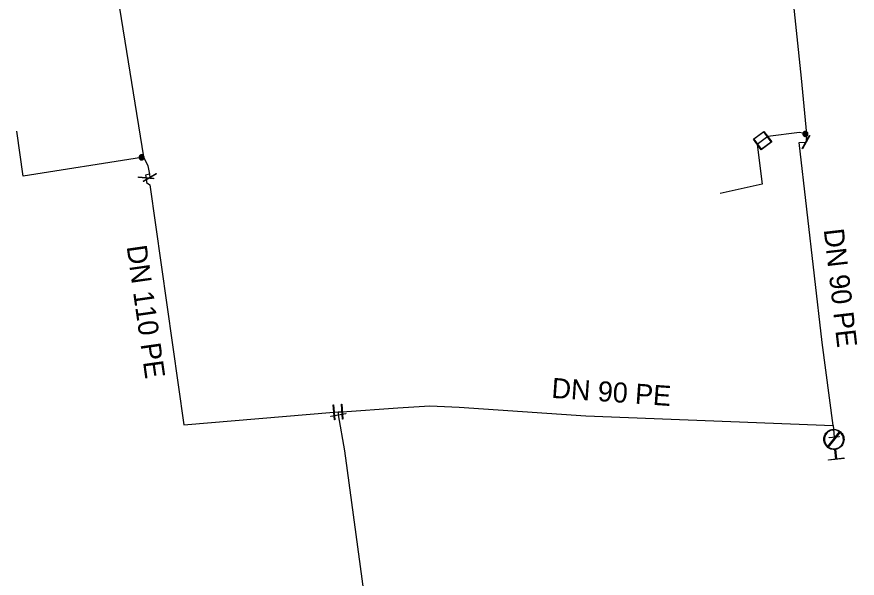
# Model space of a CAD drawing. Extents: x -832382 to -831581, y -1074670 to -1074251.
# Drawn here: x -831959.2 to -831875.6, y -1074502.9 to -1074447.1 of the extents above; entities that cross this region are included whole.
import ezdxf

# ---------------------------------------------------------------- set-up
doc = ezdxf.new("R2010")
doc.units = 0
for name, color, linetype in [('Hyd-odbočka', 7, 'Continuous'), ('Hyd-šoupě', 7, 'Continuous'), ('Hydrant', 7, 'Continuous'), ('Přípojka vodovodu', 7, 'Continuous'), ('Přípojkový uzávěr', 7, 'Continuous'), ('Roz-řad', 7, 'Continuous'), ('Roz-řad-popis základní', 7, 'Continuous'), ('Řad-šoupě', 7, 'Continuous'), ('Šachta vodovodní', 7, 'Continuous')]:
    doc.layers.add(name, color=color, linetype=linetype)

msp = doc.modelspace()

# ---------------------------------------------------------------- linework, layer by layer
at = {"layer": 'Hyd-odbočka'}
for p, q in [((-831877.96, -1074487.73), (-831877.84, -1074488.88)), ((-831877.84, -1074488.88), (-831877.88, -1074489.11))]:
    msp.add_line(p, q, dxfattribs=at)
at = {"layer": 'Hyd-šoupě'}
msp.add_lwpolyline([(-831878.339, -1074488.916), (-831877.344, -1074488.813), (-831877.341, -1074488.844), (-831878.336, -1074488.947), (-831878.339, -1074488.916)], dxfattribs=at)
at = {"layer": 'Hydrant'}
for points in [[(-831878.487, -1074489.827), (-831877.321, -1074488.353)], [(-831877.273, -1074488.393), (-831878.439, -1074489.865)], [(-831877.734, -1074490.1), (-831877.625, -1074491.031), (-831876.88, -1074490.944), (-831876.873, -1074491.006), (-831878.425, -1074491.187), (-831878.432, -1074491.125), (-831877.687, -1074491.038), (-831877.796, -1074490.107)]]:
    msp.add_lwpolyline(points, dxfattribs=at)
for points in [[(-831877.796, -1074490.107), (-831878.031, -1074490.126), (-831878.268, -1074490.032), (-831878.52, -1074489.932), (-831878.682, -1074489.708), (-831878.843, -1074489.485), (-831878.873, -1074489.225), (-831878.903, -1074488.967), (-831878.8, -1074488.715), (-831878.696, -1074488.464), (-831878.475, -1074488.305), (-831878.253, -1074488.147), (-831877.995, -1074488.117), (-831877.737, -1074488.087), (-831877.485, -1074488.19), (-831877.234, -1074488.294), (-831877.075, -1074488.515), (-831876.917, -1074488.737), (-831876.887, -1074488.995), (-831876.856, -1074489.255), (-831876.963, -1074489.509), (-831877.069, -1074489.763), (-831877.291, -1074489.918), (-831877.498, -1074490.064), (-831877.734, -1074490.1)], [(-831877.321, -1074488.353), (-831877.407, -1074488.29), (-831877.51, -1074488.249), (-831877.746, -1074488.151), (-831877.988, -1074488.179), (-831878.231, -1074488.207), (-831878.439, -1074488.356), (-831878.646, -1074488.505), (-831878.743, -1074488.74), (-831878.839, -1074488.976), (-831878.811, -1074489.218), (-831878.783, -1074489.463), (-831878.631, -1074489.671), (-831878.565, -1074489.76), (-831878.487, -1074489.827)], [(-831878.439, -1074489.865), (-831878.349, -1074489.931), (-831878.244, -1074489.974), (-831878.007, -1074490.069), (-831877.772, -1074490.041), (-831877.537, -1074490.014), (-831877.328, -1074489.868), (-831877.119, -1074489.722), (-831877.02, -1074489.484), (-831876.92, -1074489.246), (-831876.949, -1074489.002), (-831876.977, -1074488.759), (-831877.127, -1074488.553), (-831877.19, -1074488.462), (-831877.273, -1074488.393)]]:
    msp.add_open_spline(points, degree=3, dxfattribs=at)
at = {"layer": 'Přípojka vodovodu'}
for points in [[(-831946.578, -1074461.011), (-831946.757, -1074461.052), (-831958.538, -1074462.927), (-831959.174, -1074458.455)], [(-831880.618, -1074458.746), (-831880.72, -1074458.72), (-831881.288, -1074458.576), (-831884.45, -1074458.99), (-831884.983, -1074459.375)], [(-831884.983, -1074459.375), (-831885.53, -1074459.77), (-831885.03, -1074463.72), (-831889.21, -1074464.66)]]:
    msp.add_lwpolyline(points, dxfattribs=at)
at = {"layer": 'Přípojkový uzávěr'}
for points in [[(-831880.72, -1074458.47), (-831880.657, -1074458.47), (-831880.597, -1074458.502), (-831880.538, -1074458.534), (-831880.504, -1074458.595), (-831880.47, -1074458.655), (-831880.47, -1074458.72), (-831880.47, -1074458.785), (-831880.503, -1074458.845), (-831880.536, -1074458.904), (-831880.595, -1074458.937), (-831880.655, -1074458.97), (-831880.72, -1074458.97), (-831880.785, -1074458.97), (-831880.845, -1074458.937), (-831880.904, -1074458.904), (-831880.937, -1074458.845), (-831880.97, -1074458.785), (-831880.97, -1074458.72), (-831880.97, -1074458.655), (-831880.936, -1074458.595), (-831880.903, -1074458.534), (-831880.843, -1074458.502), (-831880.783, -1074458.47), (-831880.72, -1074458.47)], [(-831880.72, -1074458.493), (-831880.777, -1074458.493), (-831880.832, -1074458.523), (-831880.886, -1074458.552), (-831880.916, -1074458.606), (-831880.947, -1074458.661), (-831880.947, -1074458.72), (-831880.947, -1074458.779), (-831880.917, -1074458.833), (-831880.887, -1074458.887), (-831880.833, -1074458.917), (-831880.779, -1074458.947), (-831880.72, -1074458.947), (-831880.661, -1074458.947), (-831880.607, -1074458.917), (-831880.553, -1074458.887), (-831880.523, -1074458.833), (-831880.493, -1074458.779), (-831880.493, -1074458.72), (-831880.493, -1074458.661), (-831880.524, -1074458.606), (-831880.555, -1074458.552), (-831880.609, -1074458.523), (-831880.663, -1074458.493), (-831880.72, -1074458.493)], [(-831880.72, -1074458.511), (-831880.667, -1074458.511), (-831880.617, -1074458.538), (-831880.567, -1074458.564), (-831880.539, -1074458.615), (-831880.511, -1074458.665), (-831880.511, -1074458.72), (-831880.511, -1074458.775), (-831880.538, -1074458.824), (-831880.565, -1074458.874), (-831880.616, -1074458.902), (-831880.666, -1074458.929), (-831880.72, -1074458.929), (-831880.774, -1074458.929), (-831880.824, -1074458.902), (-831880.875, -1074458.874), (-831880.902, -1074458.824), (-831880.929, -1074458.775), (-831880.929, -1074458.72), (-831880.929, -1074458.665), (-831880.901, -1074458.615), (-831880.873, -1074458.564), (-831880.823, -1074458.538), (-831880.773, -1074458.511), (-831880.72, -1074458.511)], [(-831880.72, -1074458.533), (-831880.799, -1074458.533), (-831880.853, -1074458.587), (-831880.908, -1074458.642), (-831880.908, -1074458.72), (-831880.908, -1074458.798), (-831880.853, -1074458.853), (-831880.798, -1074458.908), (-831880.72, -1074458.908), (-831880.642, -1074458.908), (-831880.587, -1074458.853), (-831880.533, -1074458.798), (-831880.533, -1074458.72), (-831880.533, -1074458.642), (-831880.587, -1074458.587), (-831880.642, -1074458.533), (-831880.72, -1074458.533)], [(-831880.72, -1074458.555), (-831880.652, -1074458.555), (-831880.604, -1074458.603), (-831880.556, -1074458.651), (-831880.556, -1074458.72), (-831880.556, -1074458.788), (-831880.604, -1074458.836), (-831880.652, -1074458.884), (-831880.72, -1074458.884), (-831880.789, -1074458.884), (-831880.837, -1074458.836), (-831880.885, -1074458.788), (-831880.885, -1074458.72), (-831880.885, -1074458.651), (-831880.837, -1074458.603), (-831880.789, -1074458.555), (-831880.72, -1074458.555)], [(-831880.72, -1074458.575), (-831880.781, -1074458.575), (-831880.823, -1074458.617), (-831880.865, -1074458.66), (-831880.865, -1074458.72), (-831880.865, -1074458.779), (-831880.823, -1074458.822), (-831880.781, -1074458.864), (-831880.72, -1074458.864), (-831880.661, -1074458.864), (-831880.618, -1074458.822), (-831880.576, -1074458.779), (-831880.576, -1074458.72), (-831880.576, -1074458.66), (-831880.618, -1074458.617), (-831880.66, -1074458.575), (-831880.72, -1074458.575)], [(-831880.72, -1074458.595), (-831880.668, -1074458.595), (-831880.631, -1074458.632), (-831880.595, -1074458.668), (-831880.595, -1074458.72), (-831880.595, -1074458.772), (-831880.632, -1074458.809), (-831880.668, -1074458.845), (-831880.72, -1074458.845), (-831880.772, -1074458.845), (-831880.808, -1074458.809), (-831880.845, -1074458.772), (-831880.845, -1074458.72), (-831880.845, -1074458.668), (-831880.809, -1074458.632), (-831880.772, -1074458.595), (-831880.72, -1074458.595)], [(-831880.72, -1074458.618), (-831880.762, -1074458.618), (-831880.792, -1074458.648), (-831880.822, -1074458.678), (-831880.822, -1074458.72), (-831880.822, -1074458.762), (-831880.792, -1074458.792), (-831880.762, -1074458.821), (-831880.72, -1074458.821), (-831880.678, -1074458.821), (-831880.648, -1074458.792), (-831880.619, -1074458.762), (-831880.619, -1074458.72), (-831880.619, -1074458.678), (-831880.648, -1074458.648), (-831880.678, -1074458.618), (-831880.72, -1074458.618)], [(-831880.72, -1074458.636), (-831880.685, -1074458.636), (-831880.661, -1074458.66), (-831880.636, -1074458.685), (-831880.636, -1074458.72), (-831880.636, -1074458.755), (-831880.661, -1074458.779), (-831880.685, -1074458.804), (-831880.72, -1074458.804), (-831880.755, -1074458.804), (-831880.78, -1074458.779), (-831880.804, -1074458.755), (-831880.804, -1074458.72), (-831880.804, -1074458.685), (-831880.78, -1074458.66), (-831880.755, -1074458.636), (-831880.72, -1074458.636)], [(-831880.72, -1074458.658), (-831880.746, -1074458.658), (-831880.764, -1074458.676), (-831880.783, -1074458.694), (-831880.783, -1074458.72), (-831880.783, -1074458.746), (-831880.764, -1074458.764), (-831880.746, -1074458.783), (-831880.72, -1074458.783), (-831880.694, -1074458.783), (-831880.676, -1074458.764), (-831880.658, -1074458.746), (-831880.658, -1074458.72), (-831880.658, -1074458.694), (-831880.676, -1074458.676), (-831880.694, -1074458.658), (-831880.72, -1074458.658)], [(-831880.72, -1074458.681), (-831880.704, -1074458.681), (-831880.692, -1074458.692), (-831880.681, -1074458.703), (-831880.681, -1074458.72), (-831880.681, -1074458.736), (-831880.692, -1074458.748), (-831880.704, -1074458.759), (-831880.72, -1074458.759), (-831880.736, -1074458.759), (-831880.748, -1074458.748), (-831880.759, -1074458.736), (-831880.759, -1074458.72), (-831880.759, -1074458.703), (-831880.748, -1074458.692), (-831880.736, -1074458.681), (-831880.72, -1074458.681)], [(-831880.72, -1074458.697), (-831880.73, -1074458.697), (-831880.737, -1074458.703), (-831880.744, -1074458.71), (-831880.744, -1074458.72), (-831880.744, -1074458.73), (-831880.737, -1074458.737), (-831880.73, -1074458.743), (-831880.72, -1074458.743), (-831880.71, -1074458.743), (-831880.704, -1074458.737), (-831880.697, -1074458.73), (-831880.697, -1074458.72), (-831880.697, -1074458.71), (-831880.704, -1074458.703), (-831880.71, -1074458.697), (-831880.72, -1074458.697)], [(-831946.757, -1074460.802), (-831946.694, -1074460.802), (-831946.634, -1074460.834), (-831946.574, -1074460.866), (-831946.541, -1074460.927), (-831946.507, -1074460.987), (-831946.507, -1074461.052), (-831946.507, -1074461.117), (-831946.54, -1074461.177), (-831946.573, -1074461.236), (-831946.632, -1074461.269), (-831946.692, -1074461.302), (-831946.757, -1074461.302), (-831946.822, -1074461.302), (-831946.881, -1074461.269), (-831946.941, -1074461.236), (-831946.974, -1074461.177), (-831947.007, -1074461.117), (-831947.007, -1074461.052), (-831947.007, -1074460.987), (-831946.973, -1074460.927), (-831946.94, -1074460.866), (-831946.88, -1074460.834), (-831946.82, -1074460.802), (-831946.757, -1074460.802)], [(-831946.757, -1074460.825), (-831946.814, -1074460.825), (-831946.868, -1074460.855), (-831946.923, -1074460.884), (-831946.953, -1074460.938), (-831946.983, -1074460.993), (-831946.983, -1074461.052), (-831946.983, -1074461.111), (-831946.954, -1074461.165), (-831946.924, -1074461.219), (-831946.87, -1074461.249), (-831946.816, -1074461.279), (-831946.757, -1074461.279), (-831946.698, -1074461.279), (-831946.644, -1074461.249), (-831946.59, -1074461.219), (-831946.56, -1074461.165), (-831946.53, -1074461.111), (-831946.53, -1074461.052), (-831946.53, -1074460.993), (-831946.561, -1074460.938), (-831946.592, -1074460.884), (-831946.646, -1074460.855), (-831946.7, -1074460.825), (-831946.757, -1074460.825)], [(-831946.757, -1074460.842), (-831946.704, -1074460.842), (-831946.654, -1074460.869), (-831946.604, -1074460.896), (-831946.576, -1074460.947), (-831946.547, -1074460.997), (-831946.547, -1074461.052), (-831946.547, -1074461.107), (-831946.575, -1074461.156), (-831946.602, -1074461.206), (-831946.652, -1074461.234), (-831946.702, -1074461.261), (-831946.757, -1074461.261), (-831946.811, -1074461.261), (-831946.861, -1074461.234), (-831946.911, -1074461.206), (-831946.939, -1074461.156), (-831946.966, -1074461.107), (-831946.966, -1074461.052), (-831946.966, -1074460.997), (-831946.938, -1074460.947), (-831946.91, -1074460.896), (-831946.86, -1074460.869), (-831946.81, -1074460.842), (-831946.757, -1074460.842)], [(-831946.757, -1074460.864), (-831946.835, -1074460.864), (-831946.89, -1074460.919), (-831946.944, -1074460.974), (-831946.944, -1074461.052), (-831946.944, -1074461.13), (-831946.889, -1074461.185), (-831946.835, -1074461.239), (-831946.757, -1074461.239), (-831946.679, -1074461.239), (-831946.624, -1074461.185), (-831946.569, -1074461.13), (-831946.569, -1074461.052), (-831946.569, -1074460.974), (-831946.624, -1074460.919), (-831946.678, -1074460.864), (-831946.757, -1074460.864)], [(-831946.757, -1074460.887), (-831946.689, -1074460.887), (-831946.641, -1074460.935), (-831946.593, -1074460.983), (-831946.593, -1074461.051), (-831946.593, -1074461.12), (-831946.641, -1074461.168), (-831946.689, -1074461.216), (-831946.757, -1074461.216), (-831946.826, -1074461.216), (-831946.874, -1074461.168), (-831946.921, -1074461.12), (-831946.921, -1074461.051), (-831946.921, -1074460.983), (-831946.874, -1074460.935), (-831946.826, -1074460.887), (-831946.757, -1074460.887)], [(-831946.757, -1074460.907), (-831946.817, -1074460.907), (-831946.86, -1074460.949), (-831946.902, -1074460.992), (-831946.902, -1074461.051), (-831946.902, -1074461.111), (-831946.86, -1074461.154), (-831946.817, -1074461.196), (-831946.757, -1074461.196), (-831946.698, -1074461.196), (-831946.655, -1074461.154), (-831946.613, -1074461.111), (-831946.613, -1074461.051), (-831946.613, -1074460.992), (-831946.655, -1074460.949), (-831946.697, -1074460.907), (-831946.757, -1074460.907)], [(-831946.757, -1074460.927), (-831946.705, -1074460.927), (-831946.668, -1074460.964), (-831946.632, -1074461), (-831946.632, -1074461.052), (-831946.632, -1074461.104), (-831946.668, -1074461.14), (-831946.705, -1074461.177), (-831946.757, -1074461.177), (-831946.809, -1074461.177), (-831946.845, -1074461.14), (-831946.882, -1074461.104), (-831946.882, -1074461.052), (-831946.882, -1074461), (-831946.846, -1074460.964), (-831946.809, -1074460.927), (-831946.757, -1074460.927)], [(-831946.757, -1074460.95), (-831946.799, -1074460.95), (-831946.829, -1074460.98), (-831946.859, -1074461.009), (-831946.859, -1074461.052), (-831946.859, -1074461.094), (-831946.829, -1074461.124), (-831946.799, -1074461.153), (-831946.757, -1074461.153), (-831946.715, -1074461.153), (-831946.685, -1074461.124), (-831946.656, -1074461.094), (-831946.656, -1074461.052), (-831946.656, -1074461.009), (-831946.685, -1074460.98), (-831946.715, -1074460.95), (-831946.757, -1074460.95)], [(-831946.757, -1074460.967), (-831946.722, -1074460.967), (-831946.697, -1074460.992), (-831946.673, -1074461.017), (-831946.673, -1074461.052), (-831946.673, -1074461.087), (-831946.698, -1074461.111), (-831946.722, -1074461.136), (-831946.757, -1074461.136), (-831946.792, -1074461.136), (-831946.817, -1074461.111), (-831946.841, -1074461.087), (-831946.841, -1074461.052), (-831946.841, -1074461.017), (-831946.817, -1074460.992), (-831946.792, -1074460.967), (-831946.757, -1074460.967)], [(-831946.757, -1074460.989), (-831946.783, -1074460.989), (-831946.801, -1074461.008), (-831946.819, -1074461.026), (-831946.819, -1074461.052), (-831946.819, -1074461.078), (-831946.801, -1074461.096), (-831946.783, -1074461.114), (-831946.757, -1074461.114), (-831946.731, -1074461.114), (-831946.713, -1074461.096), (-831946.694, -1074461.078), (-831946.694, -1074461.052), (-831946.694, -1074461.026), (-831946.713, -1074461.008), (-831946.731, -1074460.989), (-831946.757, -1074460.989)], [(-831946.757, -1074461.013), (-831946.741, -1074461.013), (-831946.729, -1074461.024), (-831946.718, -1074461.035), (-831946.718, -1074461.052), (-831946.718, -1074461.068), (-831946.729, -1074461.08), (-831946.741, -1074461.091), (-831946.757, -1074461.091), (-831946.773, -1074461.091), (-831946.785, -1074461.08), (-831946.796, -1074461.068), (-831946.796, -1074461.052), (-831946.796, -1074461.035), (-831946.785, -1074461.024), (-831946.773, -1074461.013), (-831946.757, -1074461.013)], [(-831946.757, -1074461.029), (-831946.767, -1074461.029), (-831946.774, -1074461.035), (-831946.781, -1074461.042), (-831946.781, -1074461.052), (-831946.781, -1074461.062), (-831946.774, -1074461.069), (-831946.767, -1074461.075), (-831946.757, -1074461.075), (-831946.747, -1074461.075), (-831946.74, -1074461.069), (-831946.734, -1074461.062), (-831946.734, -1074461.052), (-831946.734, -1074461.042), (-831946.74, -1074461.035), (-831946.747, -1074461.029), (-831946.757, -1074461.029)]]:
    msp.add_open_spline(points, degree=3, dxfattribs=at)
at = {"layer": 'Roz-řad'}
for p, q in [((-831927.62, -1074486.41), (-831927.2, -1074486.36)), ((-831927.2, -1074486.36), (-831927.19, -1074486.68))]:
    msp.add_line(p, q, dxfattribs=at)
for points in [[(-831886.44, -1074408.64), (-831905.34, -1074408.59), (-831920.63, -1074409.77), (-831929.6, -1074411.16), (-831944.61, -1074414.5), (-831953.4, -1074417.02), (-831952.245, -1074422.863), (-831952.065, -1074424.626), (-831951.81, -1074427.06), (-831950.24, -1074438.21), (-831949.124, -1074445.161), (-831946.578, -1074461.011), (-831946.13, -1074461.88)], [(-831886.33, -1074408.96), (-831885.87, -1074413.25), (-831884.276, -1074422.86), (-831884.29, -1074423.69), (-831883.62, -1074429.58), (-831883.1, -1074435.36), (-831882.54, -1074441.32), (-831882.147, -1074443.657), (-831881.13, -1074453.16), (-831880.618, -1074458.746), (-831880.65, -1074459.53)], [(-831926.8, -1074486.36), (-831921.28, -1074485.98), (-831918.08, -1074485.78), (-831915.18, -1074485.91), (-831902.56, -1074486.78), (-831877.96, -1074487.73), (-831879.04, -1074479.47), (-831881.34, -1074459.58), (-831880.65, -1074459.53)], [(-831946.13, -1074461.88), (-831945.98, -1074462.73), (-831945.93, -1074463.06)], [(-831945.98, -1074462.73), (-831946.36, -1074462.81), (-831946.32, -1074463.09)], [(-831946.32, -1074463.09), (-831946.28, -1074463.54), (-831945.93, -1074463.8), (-831942.55, -1074487.65), (-831927.62, -1074486.41)], [(-831927.2, -1074486.36), (-831926.99, -1074486.36), (-831926.8, -1074486.36)], [(-831927.19, -1074486.68), (-831926.56, -1074490.26), (-831924.14, -1074508.11), (-831924.1, -1074508.45), (-831921.14, -1074530.29), (-831921.1, -1074530.55), (-831919, -1074544.28), (-831918.72, -1074546.15), (-831918.69, -1074546.67)]]:
    msp.add_lwpolyline(points, dxfattribs=at)
at = {"layer": 'Řad-šoupě'}
for points in [[(-831880.259, -1074458.89), (-831881.001, -1074460.193), (-831881.041, -1074460.17), (-831880.299, -1074458.867), (-831880.259, -1074458.89)], [(-831947.065, -1074462.998), (-831945.571, -1074463.135), (-831945.575, -1074463.182), (-831947.069, -1074463.045), (-831947.065, -1074462.998)], [(-831946.59, -1074463.418), (-831945.294, -1074462.662), (-831945.27, -1074462.702), (-831946.566, -1074463.458), (-831946.59, -1074463.418)], [(-831927.577, -1074487.159), (-831927.71, -1074485.665), (-831927.663, -1074485.661), (-831927.53, -1074487.155), (-831927.577, -1074487.159)], [(-831926.829, -1074485.61), (-831926.725, -1074487.107), (-831926.771, -1074487.11), (-831926.875, -1074485.613), (-831926.829, -1074485.61)], [(-831926.447, -1074486.573), (-831927.925, -1074486.833), (-831927.933, -1074486.787), (-831926.455, -1074486.527), (-831926.447, -1074486.573)]]:
    msp.add_lwpolyline(points, dxfattribs=at)
at = {"layer": 'Šachta vodovodní'}
for points in [[(-831884.841, -1074458.471), (-831884.072, -1074459.519), (-831885.12, -1074460.288), (-831885.889, -1074459.24), (-831884.841, -1074458.471)], [(-831885.832, -1074459.249), (-831885.111, -1074460.231), (-831884.128, -1074459.51), (-831884.849, -1074458.528), (-831885.832, -1074459.249)]]:
    msp.add_lwpolyline(points, dxfattribs=at)

# ---------------------------------------------------------------- texts
at = {"layer": 'Roz-řad-popis základní'}
for s, rotation, p in [('DN 90 PE', 276.59616, (-831878.897, -1074468.241)), ('DN 110 PE', 278.06619, (-831948.252, -1074469.915)), ('DN 90 PE', 356.05637, (-831906.02, -1074484.974))]:
    msp.add_text(s, height=2, rotation=rotation, dxfattribs=at).set_placement(p)

doc.saveas('drawing.dxf')
